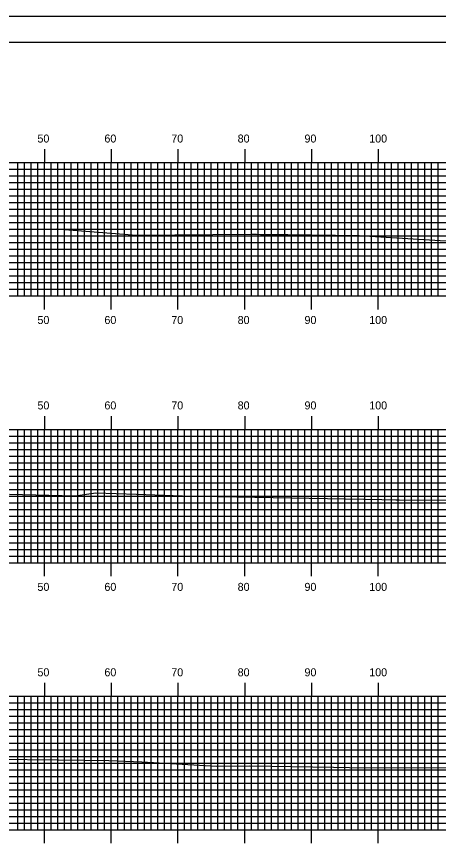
# Model space of a CAD drawing. Extents: x 1814522 to 1814865, y 442591 to 442811.
# Drawn here: x 1814733.3 to 1814796.6, y 442686.2 to 442810.5 of the extents above; entities that cross this region are included whole.
import ezdxf

# ---------------------------------------------------------------- set-up
doc = ezdxf.new("R2010")
doc.units = 0
for name, color, linetype in [('BORDER', 7, 'Continuous'), ('H_V ANNOTATION', 7, 'Continuous'), ('MAJOR', 7, 'Continuous'), ('MINOR', 7, 'Continuous'), ('PLOT BOUNDARY', 7, 'Continuous'), ('S_Roadway_Centerline', 7, 'Continuous')]:
    doc.layers.add(name, color=color, linetype=linetype)

msp = doc.modelspace()

# ---------------------------------------------------------------- linework, layer by layer
at = {"layer": 'BORDER'}
msp.add_lwpolyline([(1814537.91, 442596.67), (1814857.91, 442596.67), (1814857.91, 442806.67), (1814537.91, 442806.67)], close=True, dxfattribs=at)
at = {"layer": 'MAJOR'}
for p, q in [((1814737.51, 442790.67), (1814737.51, 442788.67)), ((1814747.51, 442790.67), (1814747.51, 442788.67)), ((1814757.51, 442790.67), (1814757.51, 442788.67)), ((1814767.51, 442790.67), (1814767.51, 442788.67)), ((1814777.51, 442790.67), (1814777.51, 442788.67)), ((1814787.51, 442790.67), (1814787.51, 442788.67)), ((1814547.51, 442788.67), (1814827.51, 442788.67)), ((1814547.51, 442788.67), (1814827.51, 442788.67)), ((1814737.51, 442768.67), (1814737.51, 442788.67)), ((1814747.51, 442768.67), (1814747.51, 442788.67)), ((1814757.51, 442768.67), (1814757.51, 442788.67)), ((1814767.51, 442768.67), (1814767.51, 442788.67)), ((1814777.51, 442768.67), (1814777.51, 442788.67)), ((1814787.51, 442768.67), (1814787.51, 442788.67)), ((1814547.51, 442783.67), (1814827.51, 442783.67)), ((1814547.51, 442778.67), (1814827.51, 442778.67)), ((1814547.51, 442773.67), (1814827.51, 442773.67)), ((1814547.51, 442768.67), (1814827.51, 442768.67)), ((1814547.51, 442768.67), (1814827.51, 442768.67)), ((1814737.51, 442766.66), (1814737.51, 442768.67)), ((1814747.51, 442766.66), (1814747.51, 442768.67)), ((1814757.51, 442766.66), (1814757.51, 442768.67)), ((1814767.51, 442766.66), (1814767.51, 442768.67)), ((1814777.51, 442766.66), (1814777.51, 442768.67)), ((1814787.51, 442766.66), (1814787.51, 442768.67)), ((1814737.51, 442750.67), (1814737.51, 442748.67)), ((1814747.51, 442750.67), (1814747.51, 442748.67)), ((1814757.51, 442750.67), (1814757.51, 442748.67)), ((1814767.51, 442750.67), (1814767.51, 442748.67)), ((1814777.51, 442750.67), (1814777.51, 442748.67)), ((1814787.51, 442750.67), (1814787.51, 442748.67)), ((1814547.51, 442748.67), (1814827.51, 442748.67)), ((1814547.51, 442748.67), (1814827.51, 442748.67)), ((1814737.51, 442728.67), (1814737.51, 442748.67)), ((1814747.51, 442728.67), (1814747.51, 442748.67)), ((1814757.51, 442728.67), (1814757.51, 442748.67)), ((1814767.51, 442728.67), (1814767.51, 442748.67)), ((1814777.51, 442728.67), (1814777.51, 442748.67)), ((1814787.51, 442728.67), (1814787.51, 442748.67)), ((1814547.51, 442743.67), (1814827.51, 442743.67)), ((1814547.51, 442738.67), (1814827.51, 442738.67)), ((1814547.51, 442733.67), (1814827.51, 442733.67)), ((1814547.51, 442728.67), (1814827.51, 442728.67)), ((1814547.51, 442728.67), (1814827.51, 442728.67)), ((1814737.51, 442726.66), (1814737.51, 442728.67)), ((1814747.51, 442726.66), (1814747.51, 442728.67)), ((1814757.51, 442726.66), (1814757.51, 442728.67)), ((1814767.51, 442726.66), (1814767.51, 442728.67)), ((1814777.51, 442726.66), (1814777.51, 442728.67)), ((1814787.51, 442726.66), (1814787.51, 442728.67)), ((1814737.51, 442710.67), (1814737.51, 442708.67)), ((1814747.51, 442710.67), (1814747.51, 442708.67)), ((1814757.51, 442710.67), (1814757.51, 442708.67)), ((1814767.51, 442710.67), (1814767.51, 442708.67)), ((1814777.51, 442710.67), (1814777.51, 442708.67)), ((1814787.51, 442710.67), (1814787.51, 442708.67)), ((1814547.51, 442708.67), (1814827.51, 442708.67)), ((1814547.51, 442708.67), (1814827.51, 442708.67)), ((1814737.51, 442688.67), (1814737.51, 442708.67)), ((1814747.51, 442688.67), (1814747.51, 442708.67)), ((1814757.51, 442688.67), (1814757.51, 442708.67)), ((1814767.51, 442688.67), (1814767.51, 442708.67)), ((1814777.51, 442688.67), (1814777.51, 442708.67)), ((1814787.51, 442688.67), (1814787.51, 442708.67)), ((1814547.51, 442703.67), (1814827.51, 442703.67)), ((1814547.51, 442698.67), (1814827.51, 442698.67)), ((1814547.51, 442693.67), (1814827.51, 442693.67)), ((1814547.51, 442688.67), (1814827.51, 442688.67)), ((1814547.51, 442688.67), (1814827.51, 442688.67)), ((1814737.51, 442686.66), (1814737.51, 442688.67)), ((1814747.51, 442686.66), (1814747.51, 442688.67)), ((1814757.51, 442686.66), (1814757.51, 442688.67)), ((1814767.51, 442686.66), (1814767.51, 442688.67)), ((1814777.51, 442686.66), (1814777.51, 442688.67)), ((1814787.51, 442686.66), (1814787.51, 442688.67))]:
    msp.add_line(p, q, dxfattribs=at)
at = {"layer": 'MINOR'}
for p, q in [((1814733.51, 442768.67), (1814733.51, 442788.67)), ((1814734.51, 442768.67), (1814734.51, 442788.67)), ((1814735.51, 442768.67), (1814735.51, 442788.67)), ((1814736.51, 442768.67), (1814736.51, 442788.67)), ((1814738.51, 442768.67), (1814738.51, 442788.67)), ((1814739.51, 442768.67), (1814739.51, 442788.67)), ((1814740.51, 442768.67), (1814740.51, 442788.67)), ((1814741.51, 442768.67), (1814741.51, 442788.67)), ((1814742.51, 442768.67), (1814742.51, 442788.67)), ((1814743.51, 442768.67), (1814743.51, 442788.67)), ((1814744.51, 442768.67), (1814744.51, 442788.67)), ((1814745.51, 442768.67), (1814745.51, 442788.67)), ((1814746.51, 442768.67), (1814746.51, 442788.67)), ((1814748.51, 442768.67), (1814748.51, 442788.67)), ((1814749.51, 442768.67), (1814749.51, 442788.67)), ((1814750.51, 442768.67), (1814750.51, 442788.67)), ((1814751.51, 442768.67), (1814751.51, 442788.67)), ((1814752.51, 442768.67), (1814752.51, 442788.67)), ((1814753.51, 442768.67), (1814753.51, 442788.67)), ((1814754.51, 442768.67), (1814754.51, 442788.67)), ((1814755.51, 442768.67), (1814755.51, 442788.67)), ((1814756.51, 442768.67), (1814756.51, 442788.67)), ((1814758.51, 442768.67), (1814758.51, 442788.67)), ((1814759.51, 442768.67), (1814759.51, 442788.67)), ((1814760.51, 442768.67), (1814760.51, 442788.67)), ((1814761.51, 442768.67), (1814761.51, 442788.67)), ((1814762.51, 442768.67), (1814762.51, 442788.67)), ((1814763.51, 442768.67), (1814763.51, 442788.67)), ((1814764.51, 442768.67), (1814764.51, 442788.67)), ((1814765.51, 442768.67), (1814765.51, 442788.67)), ((1814766.51, 442768.67), (1814766.51, 442788.67)), ((1814768.51, 442768.67), (1814768.51, 442788.67)), ((1814769.51, 442768.67), (1814769.51, 442788.67)), ((1814770.51, 442768.67), (1814770.51, 442788.67)), ((1814771.51, 442768.67), (1814771.51, 442788.67)), ((1814772.51, 442768.67), (1814772.51, 442788.67)), ((1814773.51, 442768.67), (1814773.51, 442788.67)), ((1814774.51, 442768.67), (1814774.51, 442788.67)), ((1814775.51, 442768.67), (1814775.51, 442788.67)), ((1814776.51, 442768.67), (1814776.51, 442788.67)), ((1814778.51, 442768.67), (1814778.51, 442788.67)), ((1814779.51, 442768.67), (1814779.51, 442788.67)), ((1814780.51, 442768.67), (1814780.51, 442788.67)), ((1814781.51, 442768.67), (1814781.51, 442788.67)), ((1814782.51, 442768.67), (1814782.51, 442788.67)), ((1814783.51, 442768.67), (1814783.51, 442788.67)), ((1814784.51, 442768.67), (1814784.51, 442788.67)), ((1814785.51, 442768.67), (1814785.51, 442788.67)), ((1814786.51, 442768.67), (1814786.51, 442788.67)), ((1814788.51, 442768.67), (1814788.51, 442788.67)), ((1814789.51, 442768.67), (1814789.51, 442788.67)), ((1814790.51, 442768.67), (1814790.51, 442788.67)), ((1814791.51, 442768.67), (1814791.51, 442788.67)), ((1814792.51, 442768.67), (1814792.51, 442788.67)), ((1814793.51, 442768.67), (1814793.51, 442788.67)), ((1814794.51, 442768.67), (1814794.51, 442788.67)), ((1814795.51, 442768.67), (1814795.51, 442788.67)), ((1814796.51, 442768.67), (1814796.51, 442788.67)), ((1814547.51, 442787.67), (1814827.51, 442787.67)), ((1814547.51, 442786.67), (1814827.51, 442786.67)), ((1814547.51, 442785.67), (1814827.51, 442785.67)), ((1814547.51, 442784.67), (1814827.51, 442784.67)), ((1814547.51, 442782.67), (1814827.51, 442782.67)), ((1814547.51, 442781.67), (1814827.51, 442781.67)), ((1814547.51, 442780.67), (1814827.51, 442780.67)), ((1814547.51, 442779.67), (1814827.51, 442779.67)), ((1814547.51, 442777.67), (1814827.51, 442777.67)), ((1814547.51, 442776.67), (1814827.51, 442776.67)), ((1814547.51, 442775.67), (1814827.51, 442775.67)), ((1814547.51, 442774.67), (1814827.51, 442774.67)), ((1814547.51, 442772.67), (1814827.51, 442772.67)), ((1814547.51, 442771.67), (1814827.51, 442771.67)), ((1814547.51, 442770.67), (1814827.51, 442770.67)), ((1814547.51, 442769.67), (1814827.51, 442769.67)), ((1814733.51, 442728.67), (1814733.51, 442748.67)), ((1814734.51, 442728.67), (1814734.51, 442748.67)), ((1814735.51, 442728.67), (1814735.51, 442748.67)), ((1814736.51, 442728.67), (1814736.51, 442748.67)), ((1814738.51, 442728.67), (1814738.51, 442748.67)), ((1814739.51, 442728.67), (1814739.51, 442748.67)), ((1814740.51, 442728.67), (1814740.51, 442748.67)), ((1814741.51, 442728.67), (1814741.51, 442748.67)), ((1814742.51, 442728.67), (1814742.51, 442748.67)), ((1814743.51, 442728.67), (1814743.51, 442748.67)), ((1814744.51, 442728.67), (1814744.51, 442748.67)), ((1814745.51, 442728.67), (1814745.51, 442748.67)), ((1814746.51, 442728.67), (1814746.51, 442748.67)), ((1814748.51, 442728.67), (1814748.51, 442748.67)), ((1814749.51, 442728.67), (1814749.51, 442748.67)), ((1814750.51, 442728.67), (1814750.51, 442748.67)), ((1814751.51, 442728.67), (1814751.51, 442748.67)), ((1814752.51, 442728.67), (1814752.51, 442748.67)), ((1814753.51, 442728.67), (1814753.51, 442748.67)), ((1814754.51, 442728.67), (1814754.51, 442748.67)), ((1814755.51, 442728.67), (1814755.51, 442748.67)), ((1814756.51, 442728.67), (1814756.51, 442748.67)), ((1814758.51, 442728.67), (1814758.51, 442748.67)), ((1814759.51, 442728.67), (1814759.51, 442748.67)), ((1814760.51, 442728.67), (1814760.51, 442748.67)), ((1814761.51, 442728.67), (1814761.51, 442748.67)), ((1814762.51, 442728.67), (1814762.51, 442748.67)), ((1814763.51, 442728.67), (1814763.51, 442748.67)), ((1814764.51, 442728.67), (1814764.51, 442748.67)), ((1814765.51, 442728.67), (1814765.51, 442748.67)), ((1814766.51, 442728.67), (1814766.51, 442748.67)), ((1814768.51, 442728.67), (1814768.51, 442748.67)), ((1814769.51, 442728.67), (1814769.51, 442748.67)), ((1814770.51, 442728.67), (1814770.51, 442748.67)), ((1814771.51, 442728.67), (1814771.51, 442748.67)), ((1814772.51, 442728.67), (1814772.51, 442748.67)), ((1814773.51, 442728.67), (1814773.51, 442748.67)), ((1814774.51, 442728.67), (1814774.51, 442748.67)), ((1814775.51, 442728.67), (1814775.51, 442748.67)), ((1814776.51, 442728.67), (1814776.51, 442748.67)), ((1814778.51, 442728.67), (1814778.51, 442748.67)), ((1814779.51, 442728.67), (1814779.51, 442748.67)), ((1814780.51, 442728.67), (1814780.51, 442748.67)), ((1814781.51, 442728.67), (1814781.51, 442748.67)), ((1814782.51, 442728.67), (1814782.51, 442748.67)), ((1814783.51, 442728.67), (1814783.51, 442748.67)), ((1814784.51, 442728.67), (1814784.51, 442748.67)), ((1814785.51, 442728.67), (1814785.51, 442748.67)), ((1814786.51, 442728.67), (1814786.51, 442748.67)), ((1814788.51, 442728.67), (1814788.51, 442748.67)), ((1814789.51, 442728.67), (1814789.51, 442748.67)), ((1814790.51, 442728.67), (1814790.51, 442748.67)), ((1814791.51, 442728.67), (1814791.51, 442748.67)), ((1814792.51, 442728.67), (1814792.51, 442748.67)), ((1814793.51, 442728.67), (1814793.51, 442748.67)), ((1814794.51, 442728.67), (1814794.51, 442748.67)), ((1814795.51, 442728.67), (1814795.51, 442748.67)), ((1814796.51, 442728.67), (1814796.51, 442748.67)), ((1814547.51, 442747.67), (1814827.51, 442747.67)), ((1814547.51, 442746.67), (1814827.51, 442746.67)), ((1814547.51, 442745.67), (1814827.51, 442745.67)), ((1814547.51, 442744.67), (1814827.51, 442744.67)), ((1814547.51, 442742.67), (1814827.51, 442742.67)), ((1814547.51, 442741.67), (1814827.51, 442741.67)), ((1814547.51, 442740.67), (1814827.51, 442740.67)), ((1814547.51, 442739.67), (1814827.51, 442739.67)), ((1814547.51, 442737.67), (1814827.51, 442737.67)), ((1814547.51, 442736.67), (1814827.51, 442736.67)), ((1814547.51, 442735.67), (1814827.51, 442735.67)), ((1814547.51, 442734.67), (1814827.51, 442734.67)), ((1814547.51, 442732.67), (1814827.51, 442732.67)), ((1814547.51, 442731.67), (1814827.51, 442731.67)), ((1814547.51, 442730.67), (1814827.51, 442730.67)), ((1814547.51, 442729.67), (1814827.51, 442729.67)), ((1814733.51, 442688.67), (1814733.51, 442708.67)), ((1814734.51, 442688.67), (1814734.51, 442708.67)), ((1814735.51, 442688.67), (1814735.51, 442708.67)), ((1814736.51, 442688.67), (1814736.51, 442708.67)), ((1814738.51, 442688.67), (1814738.51, 442708.67)), ((1814739.51, 442688.67), (1814739.51, 442708.67)), ((1814740.51, 442688.67), (1814740.51, 442708.67)), ((1814741.51, 442688.67), (1814741.51, 442708.67)), ((1814742.51, 442688.67), (1814742.51, 442708.67)), ((1814743.51, 442688.67), (1814743.51, 442708.67)), ((1814744.51, 442688.67), (1814744.51, 442708.67)), ((1814745.51, 442688.67), (1814745.51, 442708.67)), ((1814746.51, 442688.67), (1814746.51, 442708.67)), ((1814748.51, 442688.67), (1814748.51, 442708.67)), ((1814749.51, 442688.67), (1814749.51, 442708.67)), ((1814750.51, 442688.67), (1814750.51, 442708.67)), ((1814751.51, 442688.67), (1814751.51, 442708.67)), ((1814752.51, 442688.67), (1814752.51, 442708.67)), ((1814753.51, 442688.67), (1814753.51, 442708.67)), ((1814754.51, 442688.67), (1814754.51, 442708.67)), ((1814755.51, 442688.67), (1814755.51, 442708.67)), ((1814756.51, 442688.67), (1814756.51, 442708.67)), ((1814758.51, 442688.67), (1814758.51, 442708.67)), ((1814759.51, 442688.67), (1814759.51, 442708.67)), ((1814760.51, 442688.67), (1814760.51, 442708.67)), ((1814761.51, 442688.67), (1814761.51, 442708.67)), ((1814762.51, 442688.67), (1814762.51, 442708.67)), ((1814763.51, 442688.67), (1814763.51, 442708.67)), ((1814764.51, 442688.67), (1814764.51, 442708.67)), ((1814765.51, 442688.67), (1814765.51, 442708.67)), ((1814766.51, 442688.67), (1814766.51, 442708.67)), ((1814768.51, 442688.67), (1814768.51, 442708.67)), ((1814769.51, 442688.67), (1814769.51, 442708.67)), ((1814770.51, 442688.67), (1814770.51, 442708.67)), ((1814771.51, 442688.67), (1814771.51, 442708.67)), ((1814772.51, 442688.67), (1814772.51, 442708.67)), ((1814773.51, 442688.67), (1814773.51, 442708.67)), ((1814774.51, 442688.67), (1814774.51, 442708.67)), ((1814775.51, 442688.67), (1814775.51, 442708.67)), ((1814776.51, 442688.67), (1814776.51, 442708.67)), ((1814778.51, 442688.67), (1814778.51, 442708.67)), ((1814779.51, 442688.67), (1814779.51, 442708.67)), ((1814780.51, 442688.67), (1814780.51, 442708.67)), ((1814781.51, 442688.67), (1814781.51, 442708.67)), ((1814782.51, 442688.67), (1814782.51, 442708.67)), ((1814783.51, 442688.67), (1814783.51, 442708.67)), ((1814784.51, 442688.67), (1814784.51, 442708.67)), ((1814785.51, 442688.67), (1814785.51, 442708.67)), ((1814786.51, 442688.67), (1814786.51, 442708.67)), ((1814788.51, 442688.67), (1814788.51, 442708.67)), ((1814789.51, 442688.67), (1814789.51, 442708.67)), ((1814790.51, 442688.67), (1814790.51, 442708.67)), ((1814791.51, 442688.67), (1814791.51, 442708.67)), ((1814792.51, 442688.67), (1814792.51, 442708.67)), ((1814793.51, 442688.67), (1814793.51, 442708.67)), ((1814794.51, 442688.67), (1814794.51, 442708.67)), ((1814795.51, 442688.67), (1814795.51, 442708.67)), ((1814796.51, 442688.67), (1814796.51, 442708.67)), ((1814547.51, 442707.67), (1814827.51, 442707.67)), ((1814547.51, 442706.67), (1814827.51, 442706.67)), ((1814547.51, 442705.67), (1814827.51, 442705.67)), ((1814547.51, 442704.67), (1814827.51, 442704.67)), ((1814547.51, 442702.67), (1814827.51, 442702.67)), ((1814547.51, 442701.67), (1814827.51, 442701.67)), ((1814547.51, 442700.67), (1814827.51, 442700.67)), ((1814547.51, 442699.67), (1814827.51, 442699.67)), ((1814547.51, 442697.67), (1814827.51, 442697.67)), ((1814547.51, 442696.67), (1814827.51, 442696.67)), ((1814547.51, 442695.67), (1814827.51, 442695.67)), ((1814547.51, 442694.67), (1814827.51, 442694.67)), ((1814547.51, 442692.67), (1814827.51, 442692.67)), ((1814547.51, 442691.67), (1814827.51, 442691.67)), ((1814547.51, 442690.67), (1814827.51, 442690.67)), ((1814547.51, 442689.67), (1814827.51, 442689.67))]:
    msp.add_line(p, q, dxfattribs=at)
at = {"layer": 'PLOT BOUNDARY'}
msp.add_lwpolyline([(1814521.72, 442590.55), (1814861.72, 442590.55), (1814861.72, 442810.55), (1814521.72, 442810.55)], close=True, dxfattribs=at)
at = {"layer": 'S_Roadway_Centerline'}
for points in [[(1814726.3, 442778.47), (1814734.13, 442778.67), (1814739.24, 442778.72), (1814751.28, 442777.78), (1814768.47, 442777.95), (1814769.28, 442777.93), (1814769.86, 442777.9), (1814773.96, 442777.89), (1814784.69, 442777.72), (1814796.83, 442776.97), (1814800.62, 442776.8), (1814805.61, 442776.74), (1814817.72, 442776.47), (1814825.64, 442776.39), (1814827.51, 442776.49)], [(1814732.24, 442738.99), (1814742.09, 442738.73), (1814745.21, 442739.15), (1814751.27, 442738.99), (1814758.19, 442738.73), (1814760.89, 442738.67), (1814788.1, 442738.15), (1814790.2, 442738.11), (1814790.67, 442738.11), (1814808.22, 442738.04), (1814811.48, 442737.99), (1814824.94, 442737.73), (1814827.51, 442737.68)], [(1814730.18, 442699.25), (1814739.58, 442699.13), (1814747.15, 442699.03), (1814752.1, 442698.84), (1814763.32, 442698.18), (1814768.29, 442698.26), (1814780.81, 442698.03), (1814783.25, 442698.01), (1814814.29, 442697.92), (1814814.36, 442697.92), (1814814.62, 442697.92), (1814827.51, 442698.04)]]:
    msp.add_lwpolyline(points, dxfattribs=at)

# ---------------------------------------------------------------- texts
at = {"layer": 'H_V ANNOTATION'}
for s, p in [('50', (1814736.44, 442791.67)), ('60', (1814746.48, 442791.67)), ('70', (1814756.51, 442791.67)), ('80', (1814766.46, 442791.67)), ('90', (1814776.48, 442791.67)), ('100', (1814786.19, 442791.67)), ('50', (1814736.44, 442764.47)), ('60', (1814746.48, 442764.47)), ('70', (1814756.51, 442764.47)), ('80', (1814766.46, 442764.47)), ('90', (1814776.48, 442764.47)), ('100', (1814786.19, 442764.47)), ('50', (1814736.44, 442751.67)), ('60', (1814746.48, 442751.67)), ('70', (1814756.51, 442751.67)), ('80', (1814766.46, 442751.67)), ('90', (1814776.48, 442751.67)), ('100', (1814786.19, 442751.67)), ('50', (1814736.44, 442724.47)), ('60', (1814746.48, 442724.47)), ('70', (1814756.51, 442724.47)), ('80', (1814766.46, 442724.47)), ('90', (1814776.48, 442724.47)), ('100', (1814786.19, 442724.47)), ('50', (1814736.44, 442711.67)), ('60', (1814746.48, 442711.67)), ('70', (1814756.51, 442711.67)), ('80', (1814766.46, 442711.67)), ('90', (1814776.48, 442711.67)), ('100', (1814786.19, 442711.67))]:
    msp.add_text(s, height=1.2, dxfattribs=at).set_placement(p)

doc.saveas('drawing.dxf')
